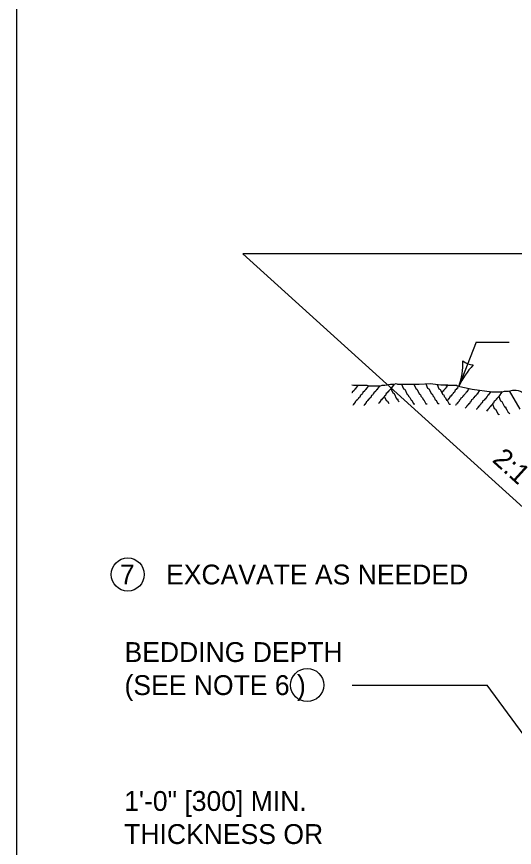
# Model space of a CAD drawing. Extents: x 49991.4 to 50021, y 49987.6 to 50011.4.
# Drawn here: x 50009.737 to 50011.243, y 50001.886 to 50004.398 of the extents above; entities that cross this region are included whole.
import ezdxf

# ---------------------------------------------------------------- set-up
doc = ezdxf.new("R2010")
doc.units = 0
for name, color, linetype in [('Level 1', 7, 'Continuous'), ('Level 2', 7, 'Continuous'), ('Level 3', 7, 'Continuous')]:
    doc.layers.add(name, color=color, linetype=linetype)

msp = doc.modelspace()

# ---------------------------------------------------------------- linework, layer by layer
at = {"layer": 'Level 1'}
for p, q in [((50011.8755, 50002.3643), (50010.4215, 50003.6812)), ((50014.1088, 50003.6812), (50010.4215, 50003.6812)), ((50011.0362, 50003.284), (50011.0484, 50003.284)), ((50011.2273, 50003.2662), (50011.26, 50003.2106))]:
    msp.add_line(p, q, dxfattribs=at)
msp.add_lwpolyline([(50020.9378, 50008.1646), (50009.7374, 50008.1646), (50009.7374, 49999.8856), (50020.9378, 49999.8856)], close=True, dxfattribs=at)
for points in [[(50010.7518, 50003.2843), (50010.7565, 50003.2831), (50010.7971, 50003.2831), (50010.8029, 50003.2812), (50010.8376, 50003.2812), (50010.8433, 50003.2831), (50010.8511, 50003.2831), (50010.8684, 50003.287), (50010.88, 50003.287), (50010.8857, 50003.2889), (50010.8896, 50003.287), (50010.9494, 50003.287), (50010.9552, 50003.287), (50010.988, 50003.2889), (50011.0207, 50003.2851), (50011.0419, 50003.2851), (50011.0477, 50003.2831), (50011.0612, 50003.2831), (50011.0689, 50003.2831), (50011.0689, 50003.2812), (50011.1152, 50003.2716), (50011.175, 50003.2639), (50011.2058, 50003.2639), (50011.2135, 50003.2658), (50011.225, 50003.2658)], [(50010.8761, 50003.287), (50010.878, 50003.285), (50010.8722, 50003.2774), (50010.8722, 50003.2754), (50010.8703, 50003.2754), (50010.8684, 50003.2716), (50010.8626, 50003.2658), (50010.8626, 50003.2639), (50010.8607, 50003.2639), (50010.8587, 50003.26), (50010.8549, 50003.2581), (50010.8529, 50003.2523), (50010.8491, 50003.2504), (50010.8491, 50003.2485), (50010.8452, 50003.2446), (50010.8452, 50003.2427), (50010.8433, 50003.2427), (50010.8414, 50003.2388), (50010.8395, 50003.2388), (50010.8395, 50003.2369), (50010.8356, 50003.233), (50010.8356, 50003.2311), (50010.8337, 50003.2311), (50010.8318, 50003.2272)], [(50010.9017, 50003.2865), (50010.9074, 50003.273), (50010.9113, 50003.2711), (50010.919, 50003.2556), (50010.921, 50003.2556), (50010.9228, 50003.2518), (50010.9228, 50003.2499), (50010.9267, 50003.246), (50010.9306, 50003.2383), (50010.9325, 50003.2383), (50010.9383, 50003.2267), (50010.9421, 50003.2267)], [(50010.9387, 50003.287), (50010.9445, 50003.2735), (50010.9484, 50003.2716), (50010.9561, 50003.2561), (50010.958, 50003.2561), (50010.96, 50003.2523), (50010.96, 50003.2504), (50010.9638, 50003.2465), (50010.9677, 50003.2388), (50010.9696, 50003.2388), (50010.9754, 50003.2272), (50010.9793, 50003.2272)], [(50010.9749, 50003.2879), (50010.9807, 50003.2745), (50010.9845, 50003.2725), (50010.9923, 50003.2571), (50010.9942, 50003.2571), (50010.9961, 50003.2533), (50010.9961, 50003.2514), (50011, 50003.2475), (50011.0038, 50003.2397), (50011.0058, 50003.2397), (50011.0115, 50003.2282), (50011.0154, 50003.2282)], [(50010.7662, 50003.2831), (50010.7682, 50003.2812), (50010.7624, 50003.2735), (50010.7624, 50003.2716), (50010.7604, 50003.2716), (50010.7585, 50003.2677), (50010.7527, 50003.262), (50010.7527, 50003.26), (50010.7518, 50003.26)], [(50010.7985, 50003.2822), (50010.8004, 50003.2803), (50010.7946, 50003.2726), (50010.7946, 50003.2706), (50010.7928, 50003.2706), (50010.7908, 50003.2668), (50010.785, 50003.261), (50010.785, 50003.259), (50010.7831, 50003.259), (50010.7812, 50003.2552), (50010.7773, 50003.2533), (50010.7753, 50003.2475), (50010.7715, 50003.2455), (50010.7715, 50003.2436), (50010.7676, 50003.2397), (50010.7676, 50003.2378), (50010.7657, 50003.2378), (50010.7638, 50003.234), (50010.7619, 50003.234), (50010.7619, 50003.232), (50010.758, 50003.2282), (50010.758, 50003.2262), (50010.7561, 50003.2262), (50010.7541, 50003.2224)], [(50010.8318, 50003.2812), (50010.8337, 50003.2793), (50010.8279, 50003.2716), (50010.8279, 50003.2696), (50010.826, 50003.2696), (50010.8241, 50003.2658), (50010.8183, 50003.26), (50010.8183, 50003.2581), (50010.8163, 50003.2581), (50010.8144, 50003.2542), (50010.8106, 50003.2523), (50010.8086, 50003.2465), (50010.8047, 50003.2446), (50010.8047, 50003.2427), (50010.8009, 50003.2388), (50010.8009, 50003.2369), (50010.799, 50003.2369), (50010.7971, 50003.233), (50010.7951, 50003.233), (50010.7951, 50003.2311), (50010.7913, 50003.2272), (50010.7913, 50003.2253), (50010.7893, 50003.2253), (50010.7874, 50003.2214)], [(50010.8694, 50003.2735), (50010.8751, 50003.26), (50010.879, 50003.2581), (50010.8867, 50003.2427), (50010.8886, 50003.2427), (50010.8906, 50003.2388), (50010.8906, 50003.2369), (50010.8941, 50003.2333)], [(50011.0091, 50003.286), (50011.0149, 50003.2725), (50011.0188, 50003.2706), (50011.0265, 50003.2552), (50011.0284, 50003.2552), (50011.0304, 50003.2514), (50011.0304, 50003.2494), (50011.0342, 50003.2455), (50011.0381, 50003.2378), (50011.04, 50003.2378), (50011.0458, 50003.2262), (50011.0496, 50003.2262)], [(50011.0415, 50003.2823), (50011.0381, 50003.2788), (50011.0381, 50003.2769), (50011.0361, 50003.2769), (50011.0342, 50003.273), (50011.0323, 50003.273), (50011.0323, 50003.2711), (50011.0284, 50003.2673), (50011.0284, 50003.2653), (50011.0265, 50003.2653), (50011.0246, 50003.2615)], [(50011.0729, 50003.2775), (50011.0713, 50003.2759), (50011.0713, 50003.274), (50011.0694, 50003.274), (50011.0674, 50003.2702), (50011.0636, 50003.2682), (50011.0616, 50003.2624), (50011.0578, 50003.2605), (50011.0578, 50003.2586), (50011.0539, 50003.2547), (50011.0539, 50003.2528), (50011.052, 50003.2528), (50011.0501, 50003.249), (50011.0482, 50003.249), (50011.0482, 50003.247), (50011.0443, 50003.2431), (50011.0443, 50003.2412), (50011.0423, 50003.2412), (50011.0404, 50003.2373)], [(50011.1026, 50003.2735), (50011.1046, 50003.2716), (50011.0988, 50003.2639), (50011.0988, 50003.262), (50011.0968, 50003.262), (50011.0949, 50003.2581), (50011.0892, 50003.2523), (50011.0892, 50003.2504), (50011.0872, 50003.2504), (50011.0853, 50003.2465), (50011.0814, 50003.2446), (50011.0795, 50003.2388), (50011.0756, 50003.2369), (50011.0756, 50003.235), (50011.0718, 50003.2311), (50011.0718, 50003.2292), (50011.0699, 50003.2292), (50011.0679, 50003.2253), (50011.066, 50003.2253), (50011.066, 50003.2234), (50011.0654, 50003.2228)], [(50011.1349, 50003.2682), (50011.1369, 50003.2662), (50011.1311, 50003.2586), (50011.1311, 50003.2566), (50011.1292, 50003.2566), (50011.1272, 50003.2528), (50011.1214, 50003.247), (50011.1214, 50003.2451), (50011.1195, 50003.2451), (50011.1176, 50003.2412), (50011.1137, 50003.2393), (50011.1117, 50003.2335), (50011.1079, 50003.2316), (50011.1079, 50003.2296), (50011.1041, 50003.2257), (50011.1041, 50003.2239), (50011.1021, 50003.2239), (50011.1002, 50003.22), (50011.0983, 50003.22), (50011.0983, 50003.2181), (50011.0944, 50003.2142)], [(50011.1687, 50003.2648), (50011.1706, 50003.2629), (50011.1648, 50003.2552), (50011.1648, 50003.2533), (50011.1629, 50003.2533), (50011.1609, 50003.2494), (50011.1552, 50003.2436), (50011.1552, 50003.2417), (50011.1532, 50003.2417), (50011.1513, 50003.2378), (50011.1475, 50003.2359), (50011.1455, 50003.2301), (50011.1416, 50003.2282), (50011.1416, 50003.2262), (50011.1378, 50003.2224), (50011.1378, 50003.2205), (50011.1359, 50003.2205), (50011.134, 50003.2166), (50011.132, 50003.2166), (50011.132, 50003.2147), (50011.1282, 50003.2108), (50011.1282, 50003.2102)], [(50011.2033, 50003.2644), (50011.2053, 50003.2624), (50011.1995, 50003.2547), (50011.1995, 50003.2528), (50011.1976, 50003.2528), (50011.1956, 50003.2489), (50011.1899, 50003.2431), (50011.1899, 50003.2412), (50011.1879, 50003.2412), (50011.186, 50003.2373), (50011.1821, 50003.2354), (50011.1802, 50003.2296), (50011.1764, 50003.2277), (50011.1764, 50003.2257), (50011.1725, 50003.2219), (50011.1725, 50003.22), (50011.1706, 50003.22), (50011.1687, 50003.2161), (50011.1667, 50003.2161), (50011.1667, 50003.2142), (50011.1629, 50003.2103), (50011.1629, 50003.2084), (50011.1609, 50003.2084), (50011.1591, 50003.2046)], [(50010.8496, 50003.2508), (50010.8554, 50003.2373), (50010.8592, 50003.2354), (50010.8629, 50003.228)], [(50011.1956, 50003.2494), (50011.2014, 50003.2359), (50011.2053, 50003.234), (50011.213, 50003.2185), (50011.2149, 50003.2185), (50011.2169, 50003.2147), (50011.2169, 50003.2128), (50011.2207, 50003.2089), (50011.2245, 50003.2012), (50011.2265, 50003.2012), (50011.2287, 50003.1968)], [(50011.1764, 50003.2267), (50011.1821, 50003.2133), (50011.186, 50003.2113), (50011.1937, 50003.1959), (50011.1957, 50003.1959), (50011.1968, 50003.1937)]]:
    msp.add_lwpolyline(points, dxfattribs=at)
msp.add_spline([(50011.225, 50003.2658), (50011.2421, 50003.2687), (50011.2664, 50003.2623), (50011.2797, 50003.2538)], degree=3, dxfattribs=at)
at = {"layer": 'Level 2'}
for centre in [(50010.0735, 50002.7111), (50010.6162, 50002.3769)]:
    msp.add_circle(centre, 0.05, dxfattribs=at)
at = {"layer": 'Level 3'}
for p, q in [((50011.1277, 50003.4139), (50011.0752, 50003.2799)), ((50011.1277, 50003.4139), (50011.2277, 50003.4139)), ((50010.7524, 50002.3766), (50011.1611, 50002.3766)), ((50011.2975, 50002.1905), (50011.1611, 50002.3766))]:
    msp.add_line(p, q, dxfattribs=at)
for centre, radius, start, end in [((50010.865, 50003.3523), 0.2223, 340.9823, 1.1658), ((50011.2877, 50003.1844), 0.233, 136.5446, 155.7945), ((50011.1219, 50003.3993), 0.0548, 230.7606, 266.483)]:
    msp.add_arc(centre, radius, start, end, dxfattribs=at)

# ---------------------------------------------------------------- texts
at = {"layer": 'Level 2'}
msp.add_text('2:1', height=0.06, rotation=317.8325, dxfattribs=at).set_placement((50011.1732, 50003.0543))
for s, p in [('7', (50010.0497, 50002.6811)), ('EXCAVATE AS NEEDED', (50010.1895, 50002.6811)), ('BEDDING DEPTH', (50010.0638, 50002.4466)), ('(SEE NOTE 6 )', (50010.0638, 50002.3466)), ('1\'-0" [300] MIN.', (50010.0628, 50001.9963)), ('THICKNESS OR', (50010.0628, 50001.8963))]:
    msp.add_text(s, height=0.06, dxfattribs=at).set_placement(p)

doc.saveas('drawing.dxf')
